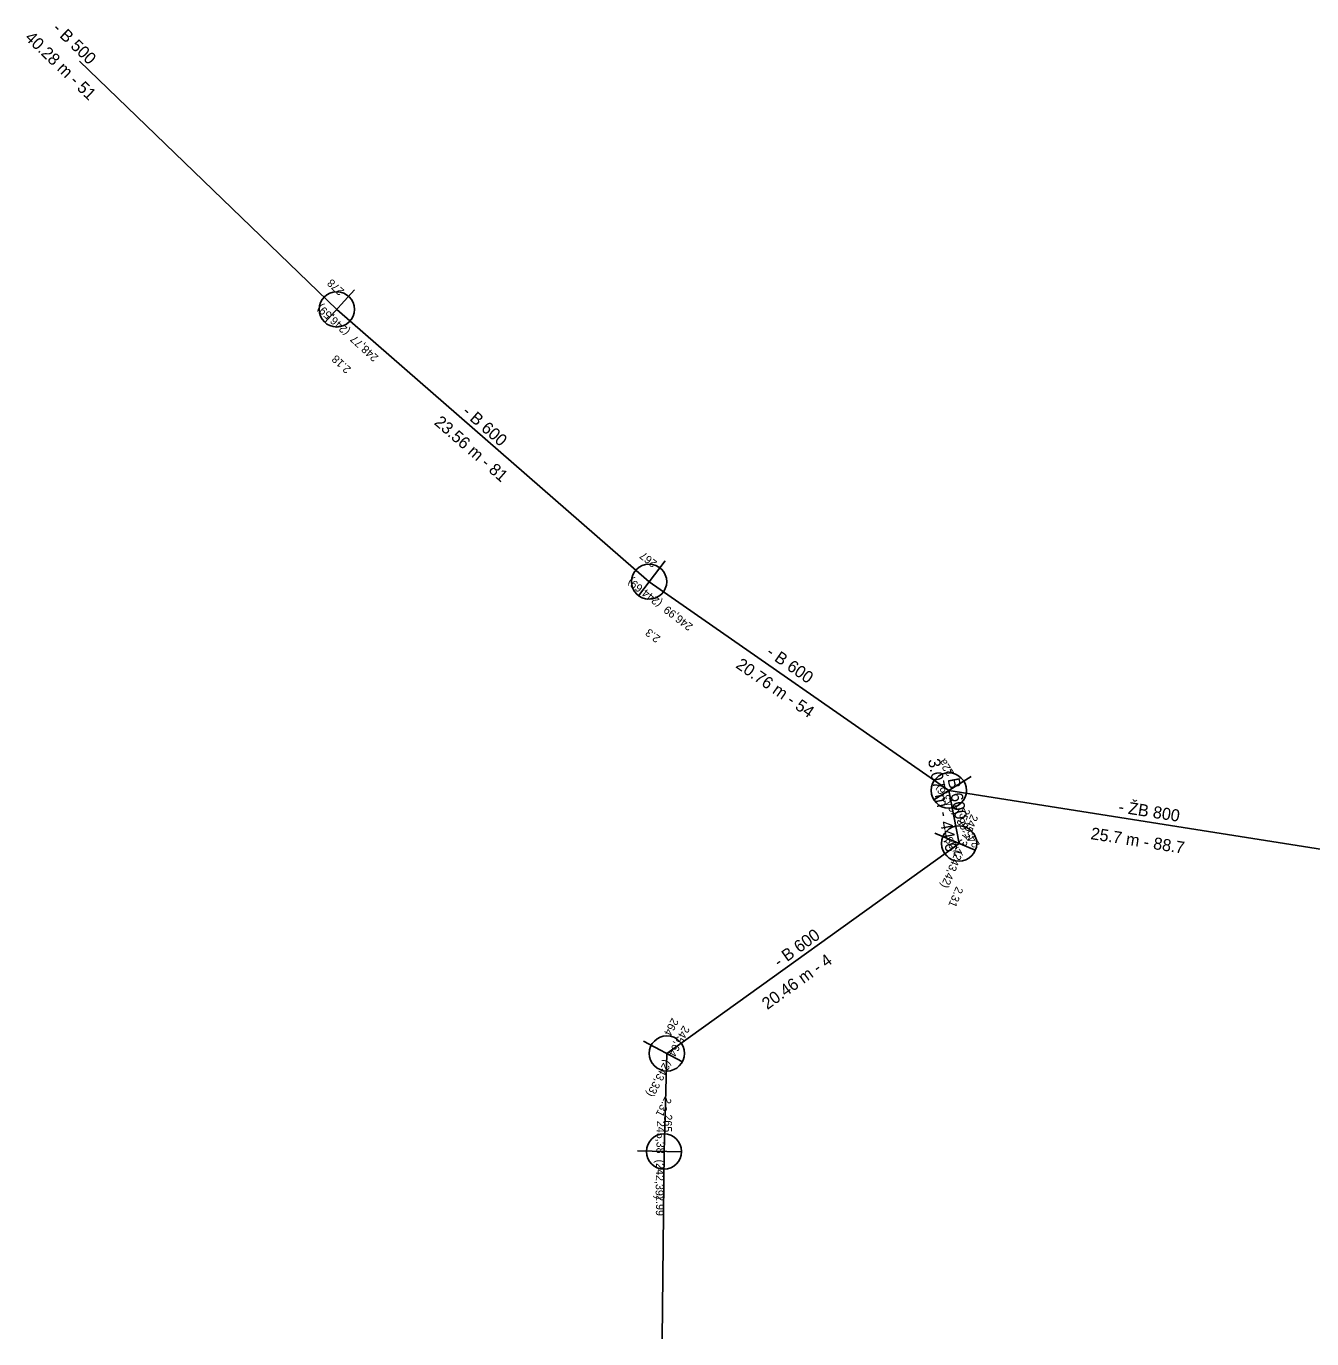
# Model space of a CAD drawing. Extents: x -600636 to -600185, y -1203957 to -1203572.
# Drawn here: x -600636.3 to -600563.2, y -1203823.2 to -1203748.6 of the extents above; entities that cross this region are included whole.
import ezdxf

# ---------------------------------------------------------------- set-up
doc = ezdxf.new("R2010")
doc.units = 0
for name, color, linetype in [('Default', 7, 'Continuous'), ('popisy_sachta_v_majetku_nebo_provozovana', 7, 'Continuous'), ('popisy_stoka', 7, 'Continuous'), ('sachta_v_majetku_nebo_provozovana', 7, 'Continuous'), ('stoka_v_majetku', 7, 'Continuous')]:
    doc.layers.add(name, color=color, linetype=linetype)

# ---------------------------------------------------------------- blocks, each defined once
blk = doc.blocks.new('MoSymbol 2')
at = {"layer": 'Default'}
blk.add_line((0, 0.00005), (0, -0.000075), dxfattribs=at)
blk.add_circle((0, 0), 0.00005, dxfattribs=at)

msp = doc.modelspace()

# ---------------------------------------------------------------- linework, layer by layer
at = {"layer": 'stoka_v_majetku'}
for p, q in [((-600633.26, -1203750.574), (-600618.628, -1203764.69)), ((-600618.628, -1203764.69), (-600600.876, -1203780.176)), ((-600600.876, -1203780.176), (-600583.84, -1203792.047)), ((-600583.84, -1203792.047), (-600583.255, -1203795.061)), ((-600583.84, -1203792.047), (-600558.458, -1203796.062)), ((-600583.255, -1203795.061), (-600599.868, -1203807.001)), ((-600599.868, -1203807.001), (-600600.029, -1203812.578)), ((-600600.029, -1203812.578), (-600600.143, -1203823.226))]:
    msp.add_line(p, q, dxfattribs=at)

# ---------------------------------------------------------------- block references
at = {"layer": 'sachta_v_majetku_nebo_provozovana'}
for p, xscale, yscale, rotation in [((-600618.628, -1203764.69), 19997.50031246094, 19997.500312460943, 137.46399104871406), ((-600600.876, -1203780.176), 19997.50031246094, 19997.500312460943, 142.4307789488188), ((-600583.84, -1203792.047), 19997.500312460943, 19997.50031246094, 122.28574105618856), ((-600583.255, -1203795.061), 19997.50031246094, 19997.500312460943, -112.84231542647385), ((-600599.868, -1203807.001), 19997.50031246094, 19997.500312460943, -117.97412332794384), ((-600600.029, -1203812.578), 19997.50031246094, 19997.50031246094, -91.13240440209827)]:
    msp.add_blockref('MoSymbol 2', p, dxfattribs=dict(at, xscale=xscale, yscale=yscale, rotation=rotation))

# ---------------------------------------------------------------- texts
at = {"layer": 'popisy_sachta_v_majetku_nebo_provozovana'}
for s, height, rotation, p in [('278', 0.4549, 137.46399, (-600618.173, -1203763.607)), ('248,77  (246,59)', 0.45494, 137.46399, (-600616.229, -1203767.373)), ('2.18', 0.4549, 137.46399, (-600617.786, -1203768.045)), ('267', 0.4549, 142.43078, (-600600.387, -1203779.052)), ('246,99  (244,69)', 0.45494, 142.43078, (-600598.349, -1203782.646)), ('2.3', 0.4549, 142.43078, (-600600.195, -1203783.326)), ('22a', 0.4549, 122.28574, (-600583.522, -1203791.05)), ('245,68  (243,6)', 0.45494, 122.28574, (-600582.055, -1203795.12)), ('245,73  (243,42)', 0.45494, 247.15768, (-600582.573, -1203793.369)), ('257', 0.4549, 247.15768, (-600583.015, -1203792.992)), ('2.08', 0.4549, 122.28574, (-600583.068, -1203795.617)), ('2.31', 0.4549, 247.15768, (-600583.418, -1203797.475)), ('245,64  (243,33)', 0.45494, 242.02588, (-600598.939, -1203805.381)), ('264', 0.4549, 242.02588, (-600599.573, -1203804.946)), ('2.31', 0.4549, 242.02588, (-600599.96, -1203809.404)), ('245,38  (242,39)', 0.45494, 268.8676, (-600600.428, -1203810.832)), ('265', 0.4549, 268.8676, (-600600.017, -1203810.461)), ('2.99', 0.4549, 268.8676, (-600600.47, -1203815.054))]:
    msp.add_text(s, height=height, rotation=rotation, dxfattribs=at).set_placement(p)
at = {"layer": 'popisy_stoka'}
for s, height, rotation, p in [('- B 500', 0.6824, 316.02788, (-600634.831, -1203748.776)), ('40.28 m - 51', 0.68241, 316.02788, (-600636.404, -1203749.289)), ('- B 600', 0.6824, 318.90011, (-600611.54, -1203770.591)), ('23.56 m - 81', 0.68241, 318.90011, (-600613.139, -1203771.184)), ('20.76 m - 54', 0.68241, 325.13111, (-600596, -1203785.023)), ('- B 600', 0.6824, 325.13111, (-600594.263, -1203784.319)), ('3.07 m - 44.6', 0.68241, 280.98676, (-600585.028, -1203790.307)), ('- B 600', 0.6824, 280.98676, (-600584.018, -1203790.849)), ('- ŽB 800', 0.6824, 351.011, (-600574.227, -1203793.285)), ('25.7 m - 88.7', 0.68241, 351.011, (-600575.81, -1203794.808)), ('- B 600', 0.6824, 35.70534, (-600593.488, -1203802.133)), ('20.46 m - 4', 0.68241, 35.70534, (-600594.158, -1203804.538))]:
    msp.add_text(s, height=height, rotation=rotation, dxfattribs=at).set_placement(p)

doc.saveas('drawing.dxf')
